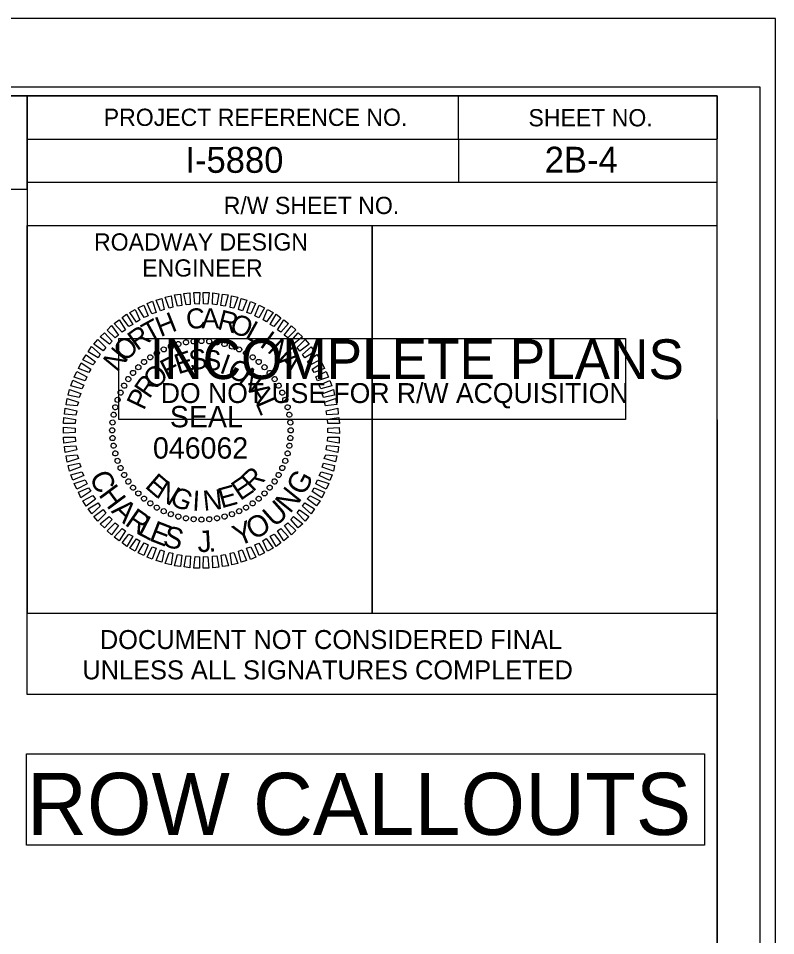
# Model space of a CAD drawing. Extents: x 1639431 to 1642602, y 841916 to 843940.
# Drawn here: x 1641668.2 to 1641887.8, y 842745.3 to 843011.3 of the extents above; entities that cross this region are included whole.
import ezdxf

# ---------------------------------------------------------------- set-up
doc = ezdxf.new("R2010")
doc.units = 0
for name, color, linetype in [('Default', 7, 'Continuous'), ('Old_Level_2', 7, 'Continuous'), ('Prop Dimension Text', 7, 'Continuous'), ('Prop DSN White Annotation Label', 7, 'Continuous'), ('Sheet Data Field CELL', 7, 'Continuous'), ('Sheet Plan CELL', 7, 'Continuous'), ('Sheet Plot Border Inside CELL', 7, 'Continuous'), ('Sheet Plot Border Outside CELL', 7, 'Continuous'), ('Sheet Sticker Exception Certification CELL', 7, 'Continuous'), ('Sheet Sticker Incomplete CELL', 7, 'Continuous')]:
    doc.layers.add(name, color=color, linetype=linetype)

msp = doc.modelspace()

# ---------------------------------------------------------------- linework, layer by layer
at = {"layer": 'Old_Level_2'}
for p, q in [((1641712.39, 842916.2), (1641712.39, 842916.2)), ((1641714.55, 842916.85), (1641714.55, 842916.85)), ((1641716.81, 842917.31), (1641716.81, 842917.31)), ((1641719.02, 842917.65), (1641719.02, 842917.65)), ((1641721.29, 842917.75), (1641721.29, 842917.75)), ((1641723.56, 842917.63), (1641723.56, 842917.63)), ((1641725.79, 842917.31), (1641725.79, 842917.31)), ((1641727.96, 842916.88), (1641727.96, 842916.88)), ((1641730.14, 842916.2), (1641730.14, 842916.2)), ((1641708.35, 842914.27), (1641708.35, 842914.27)), ((1641710.34, 842915.34), (1641710.34, 842915.34)), ((1641732.22, 842915.3), (1641732.22, 842915.3)), ((1641734.25, 842914.31), (1641734.25, 842914.31)), ((1641704.63, 842911.73), (1641704.63, 842911.73)), ((1641706.41, 842913.05), (1641706.41, 842913.05)), ((1641736.13, 842913.05), (1641736.13, 842913.05)), ((1641737.96, 842911.69), (1641737.96, 842911.69)), ((1641701.43, 842908.52), (1641701.43, 842908.52)), ((1641702.95, 842910.15), (1641702.95, 842910.15)), ((1641739.59, 842910.17), (1641739.59, 842910.17)), ((1641741.17, 842908.49), (1641741.17, 842908.49)), ((1641700.07, 842906.69), (1641700.07, 842906.69)), ((1641742.49, 842906.71), (1641742.49, 842906.71)), ((1641697.82, 842902.78), (1641697.82, 842902.78)), ((1641698.81, 842904.81), (1641698.81, 842904.81)), ((1641743.71, 842904.77), (1641743.71, 842904.77)), ((1641744.77, 842902.78), (1641744.77, 842902.78)), ((1641696.92, 842900.7), (1641696.92, 842900.7)), ((1641745.64, 842900.73), (1641745.64, 842900.73)), ((1641696.24, 842898.53), (1641696.24, 842898.53)), ((1641746.29, 842898.57), (1641746.29, 842898.57)), ((1641695.81, 842896.35), (1641695.81, 842896.35)), ((1641746.74, 842896.31), (1641746.74, 842896.31)), ((1641695.49, 842894.13), (1641695.49, 842894.13)), ((1641747.09, 842894.1), (1641747.09, 842894.1)), ((1641695.38, 842891.85), (1641695.38, 842891.85)), ((1641695.47, 842889.58), (1641695.47, 842889.58)), ((1641721.28, 842891.84), (1641721.28, 842891.84)), ((1641747.07, 842889.56), (1641747.07, 842889.56)), ((1641747.18, 842891.83), (1641747.18, 842891.83)), ((1641695.82, 842887.37), (1641695.82, 842887.37)), ((1641746.75, 842887.33), (1641746.75, 842887.33)), ((1641696.27, 842885.11), (1641696.27, 842885.11)), ((1641746.32, 842885.16), (1641746.32, 842885.16)), ((1641696.92, 842882.95), (1641696.92, 842882.95)), ((1641745.64, 842882.98), (1641745.64, 842882.98)), ((1641697.79, 842880.9), (1641697.79, 842880.9)), ((1641698.85, 842878.91), (1641698.85, 842878.91)), ((1641743.75, 842878.87), (1641743.75, 842878.87)), ((1641744.74, 842880.9), (1641744.74, 842880.9)), ((1641700.07, 842876.97), (1641700.07, 842876.97)), ((1641742.49, 842876.99), (1641742.49, 842876.99)), ((1641701.39, 842875.19), (1641701.39, 842875.19)), ((1641702.97, 842873.51), (1641702.97, 842873.51)), ((1641739.61, 842873.53), (1641739.61, 842873.53)), ((1641741.13, 842875.16), (1641741.13, 842875.16)), ((1641704.6, 842871.99), (1641704.6, 842871.99)), ((1641737.93, 842871.96), (1641737.93, 842871.96)), ((1641706.43, 842870.63), (1641706.43, 842870.63)), ((1641708.31, 842869.37), (1641708.31, 842869.37)), ((1641710.34, 842868.38), (1641710.34, 842868.38)), ((1641732.22, 842868.35), (1641732.22, 842868.35)), ((1641734.21, 842869.41), (1641734.21, 842869.41)), ((1641736.15, 842870.63), (1641736.15, 842870.63)), ((1641712.42, 842867.49), (1641712.42, 842867.49)), ((1641714.6, 842866.8), (1641714.6, 842866.8)), ((1641716.77, 842866.37), (1641716.77, 842866.37)), ((1641719, 842866.05), (1641719, 842866.05)), ((1641721.27, 842865.94), (1641721.27, 842865.94)), ((1641723.54, 842866.03), (1641723.54, 842866.03)), ((1641725.75, 842866.38), (1641725.75, 842866.38)), ((1641728.01, 842866.83), (1641728.01, 842866.83)), ((1641730.17, 842867.49), (1641730.17, 842867.49))]:
    msp.add_line(p, q, dxfattribs=at)
for points in [[(1641706.91, 842925.65), (1641705.52, 842928.62), (1641707.06, 842929.26), (1641708.2, 842925.98)], [(1641709.43, 842926.52), (1641708.19, 842929.59), (1641709.78, 842930.08), (1641710.5, 842926.9)], [(1641711.89, 842927.23), (1641710.75, 842930.46), (1641712.5, 842930.85), (1641712.97, 842927.51)], [(1641714.36, 842927.84), (1641713.47, 842931.13), (1641715.17, 842931.31), (1641715.59, 842928.02)], [(1641716.83, 842928.19), (1641716.2, 842931.49), (1641717.95, 842931.72), (1641718.06, 842928.37)], [(1641719.4, 842928.5), (1641719.09, 842931.85), (1641720.79, 842931.82), (1641720.64, 842928.47)], [(1641721.88, 842928.49), (1641721.82, 842931.84), (1641723.52, 842931.82), (1641723.12, 842928.46)], [(1641724.46, 842928.38), (1641724.61, 842931.74), (1641726.32, 842931.46), (1641725.7, 842928.19)], [(1641726.94, 842928.01), (1641727.35, 842931.32), (1641729.06, 842931.09), (1641728.18, 842927.88)], [(1641729.58, 842927.49), (1641730.04, 842930.85), (1641731.8, 842930.47), (1641730.67, 842927.25)], [(1641732.07, 842926.86), (1641732.79, 842930.07), (1641734.4, 842929.58), (1641733.16, 842926.52)], [(1641702.46, 842923.25), (1641700.51, 842926), (1641702.09, 842926.85), (1641703.43, 842923.88)], [(1641704.66, 842924.52), (1641702.96, 842927.38), (1641704.55, 842928.13), (1641705.79, 842925.01)], [(1641734.41, 842925.97), (1641735.54, 842929.24), (1641737, 842928.65), (1641735.6, 842925.63)], [(1641736.75, 842925.03), (1641737.99, 842928.1), (1641739.6, 842927.4), (1641737.89, 842924.49)], [(1641739.14, 842923.89), (1641740.48, 842926.85), (1641742.05, 842926), (1641740.13, 842923.29)], [(1641700.22, 842921.92), (1641698.26, 842924.52), (1641699.59, 842925.52), (1641701.34, 842922.56)], [(1641741.18, 842922.53), (1641742.93, 842925.55), (1641744.29, 842924.49), (1641742.32, 842921.93)], [(1641696.25, 842918.7), (1641693.94, 842920.93), (1641695.16, 842922.19), (1641697.22, 842919.44)], [(1641698.28, 842920.34), (1641696.02, 842922.77), (1641697.4, 842923.88), (1641699.25, 842921.02)], [(1641743.32, 842921.02), (1641745.18, 842923.89), (1641746.54, 842922.78), (1641744.31, 842920.31)], [(1641745.31, 842919.45), (1641747.38, 842922.17), (1641748.64, 842920.96), (1641746.3, 842918.7)], [(1641694.58, 842916.87), (1641691.91, 842918.94), (1641693.18, 842920.14), (1641695.39, 842917.71)], [(1641747.2, 842917.68), (1641749.37, 842920.14), (1641750.63, 842918.93), (1641747.99, 842916.87)], [(1641691.29, 842912.89), (1641688.48, 842914.59), (1641689.43, 842916.11), (1641691.95, 842913.88)], [(1641692.81, 842914.87), (1641690.09, 842916.84), (1641691.2, 842918.2), (1641693.51, 842915.82)], [(1641749.04, 842915.86), (1641751.37, 842918.22), (1641752.48, 842916.84), (1641749.78, 842914.84)], [(1641750.62, 842913.87), (1641753.11, 842916.08), (1641754.11, 842914.6), (1641751.25, 842912.9)], [(1641689.78, 842910.8), (1641686.87, 842912.29), (1641687.87, 842913.76), (1641690.59, 842911.74)], [(1641752, 842911.78), (1641754.7, 842913.79), (1641755.7, 842912.26), (1641752.74, 842910.76)], [(1641688.58, 842908.56), (1641685.62, 842909.8), (1641686.37, 842911.41), (1641689.18, 842909.55)], [(1641753.38, 842909.53), (1641756.23, 842911.39), (1641756.93, 842909.8), (1641754.01, 842908.56)], [(1641687.59, 842906.17), (1641684.37, 842907.3), (1641685.12, 842908.91), (1641688.09, 842907.31)], [(1641754.45, 842907.33), (1641757.46, 842908.93), (1641758.16, 842907.29), (1641754.98, 842906.21)], [(1641686.6, 842903.88), (1641683.39, 842904.75), (1641684.03, 842906.36), (1641687.15, 842904.97)], [(1641755.42, 842904.92), (1641758.54, 842906.32), (1641759.14, 842904.73), (1641755.95, 842903.85)], [(1641685.87, 842901.39), (1641682.66, 842902), (1641682.99, 842903.71), (1641686.26, 842902.48)], [(1641756.29, 842902.46), (1641759.57, 842903.71), (1641759.91, 842902.01), (1641756.67, 842901.39)], [(1641685.24, 842898.9), (1641682.04, 842899.26), (1641682.37, 842901.02), (1641685.64, 842899.99)], [(1641756.95, 842900), (1641760.18, 842901.03), (1641760.52, 842899.29), (1641757.28, 842898.92)], [(1641684.88, 842896.26), (1641681.57, 842896.51), (1641681.74, 842898.27), (1641685.11, 842897.51)], [(1641757.46, 842897.53), (1641760.8, 842898.31), (1641760.98, 842896.56), (1641757.68, 842896.3)], [(1641684.66, 842893.78), (1641681.31, 842893.83), (1641681.38, 842895.53), (1641684.74, 842895.02)], [(1641757.81, 842895.06), (1641761.16, 842895.53), (1641761.29, 842893.78), (1641757.93, 842893.82)], [(1641684.65, 842891.2), (1641681.3, 842890.99), (1641681.27, 842892.74), (1641684.63, 842892.44)], [(1641757.91, 842892.48), (1641761.26, 842892.69), (1641761.29, 842890.94), (1641757.93, 842891.24)], [(1641684.75, 842888.62), (1641681.4, 842888.15), (1641681.27, 842889.9), (1641684.63, 842889.86)], [(1641757.9, 842889.9), (1641761.25, 842889.86), (1641761.18, 842888.15), (1641757.82, 842888.66)], [(1641685.1, 842886.15), (1641681.76, 842885.37), (1641681.58, 842887.12), (1641684.88, 842887.39)], [(1641757.68, 842887.42), (1641760.99, 842887.17), (1641760.82, 842885.41), (1641757.45, 842886.18)], [(1641685.61, 842883.68), (1641682.38, 842882.65), (1641682.04, 842884.4), (1641685.28, 842884.76)], [(1641757.32, 842884.78), (1641760.52, 842884.42), (1641760.19, 842882.66), (1641756.92, 842883.69)], [(1641686.27, 842881.22), (1641682.99, 842879.98), (1641682.65, 842881.67), (1641685.89, 842882.3)], [(1641756.69, 842882.29), (1641759.9, 842881.68), (1641759.57, 842879.97), (1641756.3, 842881.2)], [(1641687.14, 842878.76), (1641684.02, 842877.36), (1641683.42, 842878.95), (1641686.61, 842879.83)], [(1641755.96, 842879.8), (1641759.17, 842878.93), (1641758.53, 842877.32), (1641755.41, 842878.71)], [(1641688.11, 842876.35), (1641685.1, 842874.75), (1641684.4, 842876.39), (1641687.58, 842877.48)], [(1641754.97, 842877.52), (1641758.19, 842876.39), (1641757.44, 842874.77), (1641754.47, 842876.37)], [(1641689.18, 842874.15), (1641686.33, 842872.29), (1641685.63, 842873.88), (1641688.55, 842875.12)], [(1641753.98, 842875.13), (1641756.94, 842873.89), (1641756.19, 842872.27), (1641753.38, 842874.13)], [(1641690.56, 842871.9), (1641687.86, 842869.89), (1641686.86, 842871.43), (1641689.82, 842872.92)], [(1641691.94, 842869.81), (1641689.45, 842867.6), (1641688.45, 842869.08), (1641691.31, 842870.78)], [(1641751.27, 842870.8), (1641754.08, 842869.09), (1641753.13, 842867.58), (1641750.61, 842869.8)], [(1641752.78, 842872.89), (1641755.69, 842871.39), (1641754.69, 842869.93), (1641751.97, 842871.94)], [(1641693.52, 842867.83), (1641691.19, 842865.46), (1641690.08, 842866.84), (1641692.78, 842868.85)], [(1641749.75, 842868.81), (1641752.47, 842866.84), (1641751.36, 842865.48), (1641749.05, 842867.87)], [(1641695.36, 842866), (1641693.19, 842863.54), (1641691.93, 842864.75), (1641694.57, 842866.81)], [(1641747.98, 842866.82), (1641750.65, 842864.75), (1641749.38, 842863.54), (1641747.17, 842865.98)], [(1641697.25, 842864.23), (1641695.18, 842861.51), (1641693.92, 842862.72), (1641696.26, 842864.98)], [(1641699.24, 842862.66), (1641697.38, 842859.79), (1641696.02, 842860.9), (1641698.25, 842863.37)], [(1641744.28, 842863.35), (1641746.54, 842860.91), (1641745.16, 842859.8), (1641743.31, 842862.66)], [(1641746.31, 842864.98), (1641748.62, 842862.75), (1641747.4, 842861.49), (1641745.34, 842864.24)], [(1641701.38, 842861.15), (1641699.63, 842858.13), (1641698.27, 842859.19), (1641700.24, 842861.75)], [(1641703.42, 842859.79), (1641702.08, 842856.83), (1641700.51, 842857.68), (1641702.43, 842860.4)], [(1641740.1, 842860.43), (1641742.05, 842857.68), (1641740.47, 842856.83), (1641739.13, 842859.8)], [(1641742.34, 842861.76), (1641744.3, 842859.17), (1641742.97, 842858.16), (1641741.22, 842861.13)], [(1641705.81, 842858.65), (1641704.57, 842855.58), (1641702.96, 842856.28), (1641704.67, 842859.2)], [(1641708.15, 842857.71), (1641707.02, 842854.44), (1641705.56, 842855.03), (1641706.96, 842858.05)], [(1641735.65, 842858.03), (1641737.04, 842855.07), (1641735.5, 842854.42), (1641734.36, 842857.7)], [(1641737.9, 842859.16), (1641739.6, 842856.3), (1641738.01, 842855.55), (1641736.77, 842858.67)], [(1641710.49, 842856.82), (1641709.77, 842853.61), (1641708.16, 842854.1), (1641709.4, 842857.16)], [(1641712.98, 842856.19), (1641712.52, 842852.83), (1641710.76, 842853.21), (1641711.89, 842856.43)], [(1641715.62, 842855.67), (1641715.21, 842852.36), (1641713.5, 842852.59), (1641714.38, 842855.81)], [(1641718.1, 842855.3), (1641717.95, 842851.95), (1641716.24, 842852.23), (1641716.86, 842855.49)], [(1641720.68, 842855.19), (1641720.74, 842851.84), (1641719.04, 842851.86), (1641719.44, 842855.22)], [(1641723.16, 842855.19), (1641723.47, 842851.84), (1641721.77, 842851.86), (1641721.92, 842855.22)], [(1641725.73, 842855.49), (1641726.36, 842852.2), (1641724.61, 842851.96), (1641724.5, 842855.31)], [(1641728.2, 842855.84), (1641729.09, 842852.55), (1641727.39, 842852.37), (1641726.97, 842855.66)], [(1641730.67, 842856.45), (1641731.81, 842853.22), (1641730.06, 842852.83), (1641729.59, 842856.17)], [(1641733.13, 842857.17), (1641734.37, 842854.09), (1641732.78, 842853.6), (1641732.06, 842856.79)]]:
    msp.add_lwpolyline(points, close=True, dxfattribs=at)
for centre, major_axis in [((1641710.34, 842915.3), (-0.314, 0.673)), ((1641712.43, 842916.16), (-0.254, 0.698)), ((1641714.58, 842916.84), (-0.192, 0.718)), ((1641716.79, 842917.33), (-0.129, 0.732)), ((1641719.02, 842917.62), (-0.065, 0.74)), ((1641721.28, 842917.72), (0, 0.743)), ((1641723.54, 842917.62), (0.065, 0.74)), ((1641725.77, 842917.33), (0.129, 0.732)), ((1641727.98, 842916.84), (0.192, 0.718)), ((1641730.13, 842916.16), (0.254, 0.698)), ((1641732.22, 842915.3), (0.314, 0.673)), ((1641706.44, 842913.04), (-0.426, 0.609)), ((1641708.34, 842914.25), (-0.371, 0.643)), ((1641734.22, 842914.25), (0.371, 0.643)), ((1641736.12, 842913.04), (0.426, 0.609)), ((1641702.98, 842910.14), (-0.525, 0.525)), ((1641704.65, 842911.67), (-0.478, 0.569)), ((1641737.91, 842911.67), (0.478, 0.569)), ((1641739.58, 842910.14), (0.525, 0.525)), ((1641701.46, 842908.48), (-0.569, 0.478)), ((1641741.1, 842908.48), (0.569, 0.478)), ((1641698.87, 842904.78), (-0.643, 0.371)), ((1641700.08, 842906.68), (-0.609, 0.426)), ((1641742.48, 842906.68), (0.609, 0.426)), ((1641743.69, 842904.78), (0.643, 0.371)), ((1641697.83, 842902.78), (-0.673, 0.314)), ((1641744.73, 842902.78), (0.673, 0.314)), ((1641696.96, 842900.69), (-0.698, 0.254)), ((1641745.6, 842900.69), (0.698, 0.254)), ((1641696.28, 842898.54), (-0.718, 0.192)), ((1641746.28, 842898.54), (0.718, 0.192)), ((1641695.5, 842894.1), (-0.74, 0.065)), ((1641695.79, 842896.34), (-0.732, 0.129)), ((1641746.77, 842896.34), (0.732, 0.129)), ((1641747.06, 842894.1), (0.74, 0.065)), ((1641695.4, 842891.84), (-0.743, 0)), ((1641747.16, 842891.84), (0.743, 0)), ((1641695.5, 842889.59), (-0.74, -0.065)), ((1641747.06, 842889.59), (0.74, -0.065)), ((1641695.79, 842887.35), (-0.732, -0.129)), ((1641746.77, 842887.35), (0.732, -0.129)), ((1641696.28, 842885.14), (-0.718, -0.192)), ((1641746.28, 842885.14), (0.718, -0.192)), ((1641696.96, 842882.99), (-0.698, -0.254)), ((1641697.83, 842880.9), (-0.673, -0.314)), ((1641744.73, 842880.9), (0.673, -0.314)), ((1641745.6, 842882.99), (0.698, -0.254)), ((1641698.87, 842878.9), (-0.643, -0.371)), ((1641743.69, 842878.9), (0.643, -0.371)), ((1641700.08, 842877), (-0.609, -0.426)), ((1641742.48, 842877), (0.609, -0.426)), ((1641701.46, 842875.21), (-0.569, -0.478)), ((1641702.98, 842873.54), (-0.525, -0.525)), ((1641739.58, 842873.54), (0.525, -0.525)), ((1641741.1, 842875.21), (0.569, -0.478)), ((1641704.65, 842872.02), (-0.478, -0.569)), ((1641706.44, 842870.64), (-0.426, -0.609)), ((1641736.12, 842870.64), (0.426, -0.609)), ((1641737.91, 842872.02), (0.478, -0.569)), ((1641708.34, 842869.43), (-0.371, -0.643)), ((1641710.34, 842868.39), (-0.314, -0.673)), ((1641712.43, 842867.52), (-0.254, -0.698)), ((1641730.13, 842867.52), (0.254, -0.698)), ((1641732.22, 842868.39), (0.314, -0.673)), ((1641734.22, 842869.43), (0.371, -0.643)), ((1641714.58, 842866.84), (-0.192, -0.718)), ((1641716.79, 842866.35), (-0.129, -0.732)), ((1641719.02, 842866.06), (-0.065, -0.74)), ((1641721.28, 842865.96), (0, -0.743)), ((1641723.54, 842866.06), (0.065, -0.74)), ((1641725.77, 842866.35), (0.129, -0.732)), ((1641727.98, 842866.84), (0.192, -0.718))]:
    msp.add_ellipse(centre, major_axis=major_axis, ratio=0.999708, dxfattribs=at)
at = {"layer": 'Prop Dimension Text'}
msp.add_lwpolyline([(1641520.72, 842961.76), (1641670.75, 842961.76), (1641670.75, 842988.83), (1641520.72, 842988.83)], close=True, dxfattribs=at)
at = {"layer": 'Prop DSN White Annotation Label'}
msp.add_lwpolyline([(1641670.57, 842798.03), (1641867.16, 842798.03), (1641867.16, 842771.55), (1641670.57, 842771.55)], close=True, dxfattribs=at)
at = {"layer": 'Sheet Plan CELL'}
for p, q in [((1641795.76, 842988.76), (1641795.81, 842963.76)), ((1641670.74, 842976.28), (1641870.79, 842976.27)), ((1641670.75, 842963.74), (1641870.79, 842963.77)), ((1641670.75, 842963.74), (1641870.79, 842963.77)), ((1641670.75, 842963.74), (1641670.75, 842951.26)), ((1641770.8, 842951.26), (1641770.81, 842838.79))]:
    msp.add_line(p, q, dxfattribs=at)
for points in [[(1640370.79, 841938.82), (1640370.76, 842988.79), (1641670.75, 842988.83), (1641670.76, 842838.77), (1641870.8, 842838.76), (1641870.8, 841938.82)], [(1641870.83, 842988.82), (1640370.79, 842988.82), (1640370.79, 841938.82), (1641870.8, 841938.82)], [(1641670.75, 842988.83), (1641870.83, 842988.82), (1641870.79, 842963.77), (1641670.75, 842963.74)], [(1641670.75, 842951.26), (1641770.8, 842951.26), (1641770.8, 842838.74), (1641670.76, 842838.77)], [(1641770.8, 842951.26), (1641870.79, 842951.27), (1641870.8, 842838.76), (1641770.8, 842838.74)]]:
    msp.add_lwpolyline(points, close=True, dxfattribs=at)
at = {"layer": 'Sheet Plot Border Inside CELL'}
msp.add_lwpolyline([(1640217.3, 841936.31), (1641883.29, 841936.32), (1641883.3, 842991.31), (1640217.3, 842991.31)], close=True, dxfattribs=at)
at = {"layer": 'Sheet Plot Border Outside CELL'}
msp.add_lwpolyline([(1640204.3, 841916.31), (1641887.8, 841916.31), (1641887.8, 843011.31), (1640204.3, 843011.31)], close=True, dxfattribs=at)
msp.add_lwpolyline([(1640204.3, 841916.31), (1641887.8, 841916.31), (1641887.8, 843011.31), (1640204.3, 843011.31)], close=True, dxfattribs=at)
at = {"layer": 'Sheet Sticker Exception Certification CELL'}
for p, q in [((1641670.76, 842815.27), (1641670.76, 842838.77)), ((1641670.76, 842838.77), (1641870.8, 842838.77)), ((1641670.76, 842815.27), (1641670.76, 842838.77)), ((1641670.76, 842838.77), (1641870.8, 842838.77)), ((1641870.8, 842838.76), (1641870.8, 842815.26)), ((1641870.8, 842838.76), (1641870.8, 842815.26)), ((1641870.8, 842815.27), (1641670.76, 842815.27)), ((1641870.8, 842815.27), (1641670.76, 842815.27))]:
    msp.add_line(p, q, dxfattribs=at)
at = {"layer": 'Sheet Sticker Incomplete CELL'}
msp.add_lwpolyline([(1641697.3, 842895.01), (1641697.3, 842918.51), (1641844.3, 842918.51), (1641844.3, 842895.01)], close=True, dxfattribs=at)

# ---------------------------------------------------------------- texts
at = {"layer": 'Default'}
for s, rotation, p in [('C', 297.1999, (1641688.6, 842878.29)), ('G', 61.7998, (1641750.99, 842872.6)), ('H', 306.6436, (1641691.26, 842873.11)), ('N', 51.2288, (1641746.96, 842867.48)), ('A', 316.4834, (1641694.9, 842868.26)), ('U', 41.4347, (1641742.45, 842863.47)), ('R', 325.1961, (1641698.78, 842864.53)), ('L', 332.5683, (1641702.47, 842861.87)), ('E', 338.7525, (1641705.8, 842860.02)), ('Y', 22.2426, (1641731.95, 842858.09)), ('O', 30.0413, (1641736.43, 842859.85)), ('S', 345.7591, (1641709.8, 842858.36)), ('J', 3.0321, (1641720.25, 842856.46)), ('.', 8.214, (1641723.45, 842856.51))]:
    msp.add_text(s, height=6.19, rotation=rotation, dxfattribs=at).set_placement(p)
at = {"layer": 'Old_Level_2'}
for s, rotation, p in [('C', 7.2199, (1641717.21, 842921.03)), ('A', 0.0203, (1641721.28, 842921.41)), ('R', 345.6211, (1641725.62, 842921.28)), ('T', 28.8198, (1641706.08, 842917.07)), ('H', 21.6195, (1641709.4, 842918.83)), ('O', 338.4212, (1641729.09, 842920.56)), ('R', 36.0205, (1641702.61, 842914.74)), ('L', 331.2209, (1641733.66, 842918.74)), ('O', 43.2217, (1641699.11, 842911.48)), ('I', 324.0201, (1641737.88, 842916.33)), ('N', 50.4235, (1641696.79, 842908.44)), ('N', 316.8189, (1641740.13, 842914.77)), ('F', 26.967, (1641711.27, 842906.42)), ('E', 17.6111, (1641714.55, 842908.03)), ('S', 8.2556, (1641718.09, 842909.18)), ('S', 358.9004, (1641721.8, 842909.29)), ('I', 340.1896, (1641726.25, 842908.65)), ('A', 309.6172, (1641743.22, 842911.78)), ('O', 330.8335, (1641728.33, 842907.96)), ('O', 45.6812, (1641707.92, 842903.32)), ('N', 321.4766, (1641731.82, 842905.96)), ('R', 55.0397, (1641706.16, 842900.76)), ('P', 64.3989, (1641704.57, 842897.43)), ('A', 302.7603, (1641734.81, 842903.33)), ('L', 293.4009, (1641736.88, 842899.8)), ('E', 319.2769, (1641704.64, 842875.4)), ('E', 34.1241, (1641732.53, 842871.29)), ('R', 43.4814, (1641736.15, 842873.78)), ('N', 328.634, (1641707.79, 842872.67)), ('E', 15.4118, (1641727.09, 842869.19)), ('G', 337.9902, (1641711.75, 842870.41)), ('I', 356.7012, (1641718.54, 842868.57)), ('N', 6.0564, (1641722, 842868.48))]:
    msp.add_text(s, height=5.82, rotation=rotation, dxfattribs=at).set_placement(p)
for s, height, p in [('SEAL', 6.189, (1641712.13, 842892.71)), ('046062', 6.191, (1641707.22, 842883.63))]:
    msp.add_text(s, height=height, dxfattribs=at).set_placement(p)
at = {"layer": 'Prop DSN White Annotation Label'}
msp.add_text('ROW CALLOUTS', height=18, rotation=360, dxfattribs=at).set_placement((1641670.7, 842774.51))
at = {"layer": 'Sheet Data Field CELL'}
for s, p in [('I-5880', (1641716.62, 842966.51)), ('2B-4', (1641820.84, 842966.57))]:
    msp.add_text(s, height=7.5, rotation=0, dxfattribs=at).set_placement(p)
at = {"layer": 'Sheet Plan CELL'}
for s, height, p in [('PROJECT REFERENCE NO.', 5.0001, (1641692.95, 842980.11)), ('SHEET NO.', 5, (1641816.11, 842979.99)), ('R/W SHEET NO.', 5.0001, (1641727.75, 842954.56)), ('ROADWAY DESIGN', 5.0001, (1641690.13, 842943.96)), ('ENGINEER', 5, (1641704.11, 842936.42))]:
    msp.add_text(s, height=height, rotation=0, dxfattribs=at).set_placement(p)
at = {"layer": 'Sheet Sticker Exception Certification CELL'}
for s, p in [('DOCUMENT NOT CONSIDERED FINAL', (1641691.83, 842828.42)), ('DOCUMENT NOT CONSIDERED FINAL', (1641691.83, 842828.42)), ('UNLESS ALL SIGNATURES COMPLETED', (1641686.76, 842819.62)), ('UNLESS ALL SIGNATURES COMPLETED', (1641686.76, 842819.62))]:
    msp.add_text(s, height=5.5, rotation=360, dxfattribs=at).set_placement(p)
at = {"layer": 'Sheet Sticker Incomplete CELL'}
for s, height, p in [('INCOMPLETE PLANS', 11.52, (1641706.25, 842906.71)), ('DO NOT USE FOR R/W ACQUISITION', 5.76, (1641709.5, 842899.76))]:
    msp.add_text(s, height=height, rotation=360, dxfattribs=at).set_placement(p)

doc.saveas('drawing.dxf')
